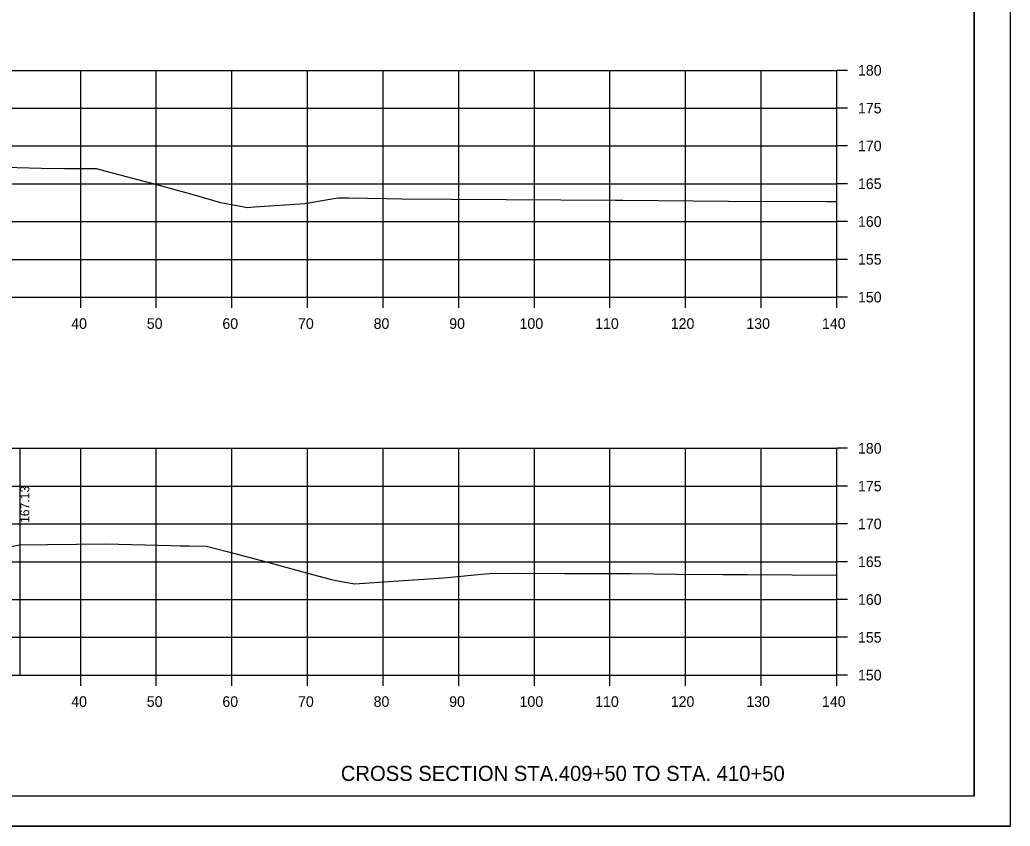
# Model space of a CAD drawing. Extents: x 1368503 to 1373085, y 379840 to 381833.
# Drawn here: x 1372954 to 1373085, y 381241.7 to 381348.3 of the extents above; entities that cross this region are included whole.
import ezdxf

# ---------------------------------------------------------------- set-up
doc = ezdxf.new("R2010")
doc.units = 0
for name, color, linetype in [('S_BRIDGE', 7, 'Continuous'), ('S_EDGE_PAVEMENT', 7, 'Continuous'), ('S_MISC_BOUNDARY', 7, 'Continuous'), ('S_PHOTO_CENTERS', 7, 'Continuous'), ('S_PHOTO_NOTES', 7, 'Continuous'), ('S_SHOULDER', 7, 'Continuous'), ('S_TRAILS', 7, 'Continuous'), ('S_TREE', 7, 'Continuous')]:
    doc.layers.add(name, color=color, linetype=linetype)

msp = doc.modelspace()

# ---------------------------------------------------------------- linework, layer by layer
at = {"layer": 'S_BRIDGE'}
for q in [(1373080.26, 381451.1), (1372764.08, 381245.64)]:
    msp.add_line((1373080.26, 381245.64), q, dxfattribs=at)
at = {"layer": 'S_EDGE_PAVEMENT'}
for p, q in [((1373062.08, 381311.64), (1373062.08, 381341.64)), ((1373063.48, 381341.64), (1373062.08, 381341.64)), ((1373063.48, 381336.64), (1373062.08, 381336.64)), ((1373063.48, 381331.64), (1373062.08, 381331.64)), ((1373063.48, 381326.64), (1373062.08, 381326.64)), ((1373063.48, 381321.64), (1373062.08, 381321.64)), ((1373063.48, 381316.64), (1373062.08, 381316.64)), ((1372782.08, 381311.64), (1373062.08, 381311.64)), ((1372962.08, 381310.24), (1372962.08, 381311.64)), ((1372972.08, 381310.24), (1372972.08, 381311.64)), ((1372982.08, 381310.24), (1372982.08, 381311.64)), ((1372992.08, 381310.24), (1372992.08, 381311.64)), ((1373002.08, 381310.24), (1373002.08, 381311.64)), ((1373012.08, 381310.24), (1373012.08, 381311.64)), ((1373022.08, 381310.24), (1373022.08, 381311.64)), ((1373032.08, 381310.24), (1373032.08, 381311.64)), ((1373042.08, 381310.24), (1373042.08, 381311.64)), ((1373052.08, 381310.24), (1373052.08, 381311.64)), ((1373062.08, 381310.24), (1373062.08, 381311.64)), ((1373063.48, 381311.64), (1373062.08, 381311.64)), ((1373062.08, 381261.64), (1373062.08, 381291.64)), ((1373063.48, 381291.64), (1373062.08, 381291.64)), ((1373063.48, 381286.64), (1373062.08, 381286.64)), ((1373063.48, 381281.64), (1373062.08, 381281.64)), ((1373063.48, 381276.64), (1373062.08, 381276.64)), ((1373063.48, 381271.64), (1373062.08, 381271.64)), ((1373063.48, 381266.64), (1373062.08, 381266.64)), ((1372782.08, 381261.64), (1373062.08, 381261.64)), ((1372962.08, 381260.24), (1372962.08, 381261.64)), ((1372972.08, 381260.24), (1372972.08, 381261.64)), ((1372982.08, 381260.24), (1372982.08, 381261.64)), ((1372992.08, 381260.24), (1372992.08, 381261.64)), ((1373002.08, 381260.24), (1373002.08, 381261.64)), ((1373012.08, 381260.24), (1373012.08, 381261.64)), ((1373022.08, 381260.24), (1373022.08, 381261.64)), ((1373032.08, 381260.24), (1373032.08, 381261.64)), ((1373042.08, 381260.24), (1373042.08, 381261.64)), ((1373052.08, 381260.24), (1373052.08, 381261.64)), ((1373062.08, 381260.24), (1373062.08, 381261.64)), ((1373063.48, 381261.64), (1373062.08, 381261.64))]:
    msp.add_line(p, q, dxfattribs=at)
at = {"layer": 'S_MISC_BOUNDARY'}
for points in [[(1372950.39, 381328.88), (1372956.88, 381328.72), (1372959.97, 381328.65), (1372963.82, 381328.64), (1372964.12, 381328.65), (1372965.58, 381328.26), (1372972.3, 381326.48), (1372977.07, 381325.19), (1372980.56, 381324.18), (1372983.46, 381323.63), (1372984.09, 381323.5), (1372985.07, 381323.58), (1372991.71, 381324.03), (1372995.03, 381324.6), (1372996.15, 381324.79), (1372997.49, 381324.77), (1373002.54, 381324.67), (1373004.54, 381324.65), (1373011.12, 381324.61), (1373032.83, 381324.48), (1373033.16, 381324.48), (1373033.78, 381324.47), (1373047.77, 381324.34), (1373060.78, 381324.28), (1373062.08, 381324.28)], [(1372950.02, 381278.17), (1372954.07, 381278.87), (1372957.68, 381278.9), (1372965.35, 381278.99), (1372974.02, 381278.77), (1372975.21, 381278.74), (1372976.49, 381278.73), (1372978.71, 381278.7), (1372981.46, 381278), (1372986.95, 381276.53), (1372992.74, 381274.95), (1372995.26, 381274.27), (1372996.79, 381274), (1372998.33, 381273.72), (1373002.8, 381274.01), (1373010.09, 381274.53), (1373015.1, 381274.98), (1373016.14, 381275.07), (1373019.35, 381275.12), (1373026.13, 381275.1), (1373034.87, 381275.08), (1373040.87, 381275), (1373047.02, 381274.94), (1373050.27, 381274.94), (1373062.08, 381274.88)]]:
    msp.add_lwpolyline(points, dxfattribs=at)
at = {"layer": 'S_PHOTO_CENTERS'}
for p, q in [((1372782.08, 381341.64), (1373062.08, 381341.64)), ((1372962.08, 381311.64), (1372962.08, 381341.64)), ((1372972.08, 381311.64), (1372972.08, 381341.64)), ((1372982.08, 381311.64), (1372982.08, 381341.64)), ((1372992.08, 381311.64), (1372992.08, 381341.64)), ((1373002.08, 381311.64), (1373002.08, 381341.64)), ((1373012.08, 381311.64), (1373012.08, 381341.64)), ((1373022.08, 381311.64), (1373022.08, 381341.64)), ((1373032.08, 381311.64), (1373032.08, 381341.64)), ((1373042.08, 381311.64), (1373042.08, 381341.64)), ((1373052.08, 381311.64), (1373052.08, 381341.64)), ((1373062.08, 381311.64), (1373062.08, 381341.64)), ((1372782.08, 381336.64), (1373062.08, 381336.64)), ((1372782.08, 381331.64), (1373062.08, 381331.64)), ((1372782.08, 381326.64), (1373062.08, 381326.64)), ((1372782.08, 381321.64), (1373062.08, 381321.64)), ((1372782.08, 381316.64), (1373062.08, 381316.64)), ((1372782.08, 381311.64), (1373062.08, 381311.64)), ((1372782.08, 381291.64), (1373062.08, 381291.64)), ((1372962.08, 381261.64), (1372962.08, 381291.64)), ((1372972.08, 381261.64), (1372972.08, 381291.64)), ((1372982.08, 381261.64), (1372982.08, 381291.64)), ((1372992.08, 381261.64), (1372992.08, 381291.64)), ((1373002.08, 381261.64), (1373002.08, 381291.64)), ((1373012.08, 381261.64), (1373012.08, 381291.64)), ((1373022.08, 381261.64), (1373022.08, 381291.64)), ((1373032.08, 381261.64), (1373032.08, 381291.64)), ((1373042.08, 381261.64), (1373042.08, 381291.64)), ((1373052.08, 381261.64), (1373052.08, 381291.64)), ((1373062.08, 381261.64), (1373062.08, 381291.64)), ((1372782.08, 381286.64), (1373062.08, 381286.64)), ((1372782.08, 381281.64), (1373062.08, 381281.64)), ((1372782.08, 381276.64), (1373062.08, 381276.64)), ((1372782.08, 381271.64), (1373062.08, 381271.64)), ((1372782.08, 381266.64), (1373062.08, 381266.64)), ((1372782.08, 381261.64), (1373062.08, 381261.64))]:
    msp.add_line(p, q, dxfattribs=at)
at = {"layer": 'S_PHOTO_NOTES'}
for p, q in [((1372954.08, 381261.64), (1372954.08, 381291.64)), ((1372751.68, 381241.66), (1373085.01, 381241.66))]:
    msp.add_line(p, q, dxfattribs=at)
for points in [[(1372751.67, 381454.99), (1373085.01, 381454.99), (1373085.01, 381241.66), (1372751.67, 381241.66)], [(1372998, 381451.1), (1372998, 381441.22), (1373033.73, 381441.22), (1373033.73, 381438.3), (1373056.93, 381438.3), (1373056.93, 381413.97), (1373080.26, 381413.97), (1373080.26, 381245.64), (1372764.08, 381245.64), (1372764.08, 381451.1)]]:
    msp.add_lwpolyline(points, close=True, dxfattribs=at)

# ---------------------------------------------------------------- texts
at = {"layer": 'S_SHOULDER'}
msp.add_text('167.13', height=1.2, rotation=90, dxfattribs=at).set_placement((1372955.28, 381281.77))
at = {"layer": 'S_TRAILS'}
for s, p in [('180', (1373064.88, 381340.94)), ('175', (1373064.88, 381335.94)), ('170', (1373064.88, 381330.94)), ('165', (1373064.88, 381325.94)), ('160', (1373064.88, 381320.94)), ('155', (1373064.88, 381315.94)), ('150', (1373064.88, 381310.94)), ('40', (1372960.82, 381307.44)), ('50', (1372970.82, 381307.44)), ('60', (1372980.82, 381307.44)), ('70', (1372990.82, 381307.44)), ('80', (1373000.82, 381307.44)), ('90', (1373010.82, 381307.44)), ('100', (1373020.12, 381307.44)), ('110', (1373030.12, 381307.44)), ('120', (1373040.12, 381307.44)), ('130', (1373050.12, 381307.44)), ('140', (1373060.12, 381307.44)), ('180', (1373064.88, 381290.94)), ('175', (1373064.88, 381285.94)), ('170', (1373064.88, 381280.94)), ('165', (1373064.88, 381275.94)), ('160', (1373064.88, 381270.94)), ('155', (1373064.88, 381265.94)), ('150', (1373064.88, 381260.94)), ('40', (1372960.82, 381257.44)), ('50', (1372970.82, 381257.44)), ('60', (1372980.82, 381257.44)), ('70', (1372990.82, 381257.44)), ('80', (1373000.82, 381257.44)), ('90', (1373010.82, 381257.44)), ('100', (1373020.12, 381257.44)), ('110', (1373030.12, 381257.44)), ('120', (1373040.12, 381257.44)), ('130', (1373050.12, 381257.44)), ('140', (1373060.12, 381257.44))]:
    msp.add_text(s, height=1.4, dxfattribs=at).set_placement(p)
at = {"layer": 'S_TREE'}
msp.add_text('CROSS SECTION STA.409+50 TO STA. 410+50', height=2, dxfattribs=at).set_placement((1372996.48, 381247.64))

doc.saveas('drawing.dxf')
